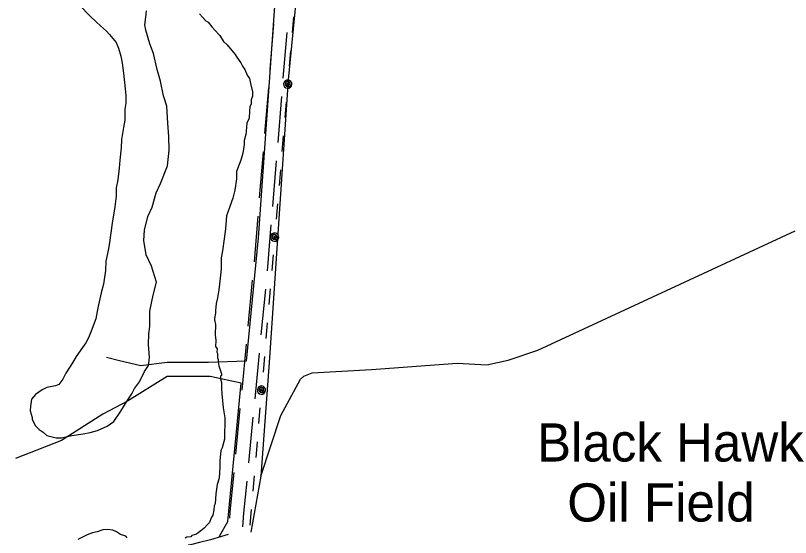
# Model space of a CAD drawing. Extents: x 3172231 to 3210228, y 940198 to 965780.
# Drawn here: x 3182155 to 3183839, y 956390 to 957526 of the extents above; entities that cross this region are included whole.
import ezdxf

# ---------------------------------------------------------------- set-up
doc = ezdxf.new("R2010")
doc.units = 0
for name, color, linetype in [('V-ROAD-CNTR', 7, 'Continuous'), ('V-SITE-VEGE', 7, 'Continuous'), ('V-TOPO-GNAM-IDEN', 7, 'Continuous'), ('V-TOPO-SHOR', 7, 'Continuous'), ('V-UTIL-LINE', 7, 'Continuous')]:
    doc.layers.add(name, color=color, linetype=linetype)

msp = doc.modelspace()

# ---------------------------------------------------------------- linework, layer by layer
at = {"layer": 'V-ROAD-CNTR'}
for p, q in [((3182708.529, 957408.331), (3182716.704, 957507.996)), ((3182737.064, 957389.243), (3182745.239, 957488.908)), ((3182697.084, 957268.799), (3182705.259, 957368.464)), ((3182725.62, 957249.712), (3182733.794, 957349.377)), ((3182685.64, 957129.268), (3182693.814, 957228.933)), ((3182714.175, 957110.18), (3182722.35, 957209.846)), ((3182674.195, 956989.736), (3182682.37, 957089.402)), ((3182660.834, 956850.376), (3182670.464, 956949.911)), ((3182689.13, 956831.31), (3182698.759, 956930.845)), ((3182647.353, 956711.027), (3182656.983, 956810.562)), ((3182675.649, 956691.961), (3182685.278, 956791.496)), ((3182633.872, 956571.677), (3182643.501, 956671.213)), ((3182662.167, 956552.611), (3182671.797, 956652.146))]:
    msp.add_line(p, q, dxfattribs=at)
for points in [[(3182702.611, 956970.659), (3182703.398, 956978.793), (3182710.905, 957070.314)], [(3182620.674, 956432.303), (3182621.717, 956446.036), (3182630.02, 956531.863)], [(3182649.31, 956413.208), (3182651.607, 956443.456), (3182658.316, 956512.797)], [(3182617.121, 956396.479), (3182602.992, 956392.242), (3182579.141, 956385.535), (3182555.135, 956379.231), (3182535.32, 956374.275), (3182535.32, 956374.569), (3182530.657, 956373.521)]]:
    msp.add_lwpolyline(points, dxfattribs=at)
at = {"layer": 'V-SITE-VEGE'}
for points in [[(3182359.713, 957032.154), (3182357.548, 957017.909), (3182351.195, 956991.473), (3182351.013, 956971.097), (3182346.671, 956941.588), (3182341.402, 956922.275), (3182333.978, 956889.737), (3182329.691, 956866.338), (3182319.254, 956838.922), (3182314.032, 956824.702), (3182307.818, 956813.551), (3182300.595, 956803.426), (3182287.175, 956784.185), (3182278.897, 956769.996), (3182264.432, 956747.71), (3182258.197, 956734.521), (3182248.928, 956723.396), (3182241.768, 956720.404), (3182223.392, 956716.492), (3182213.16, 956711.491), (3182198.801, 956701.429), (3182189.538, 956691.326), (3182187.365, 956676.058), (3182187.275, 956665.872), (3182191.222, 956651.571), (3182191.185, 956647.495), (3182198.197, 956634.185), (3182206.266, 956624.942), (3182215.39, 956619.765), (3182223.478, 956612.56), (3182243.806, 956607.283), (3182255.015, 956607.182), (3182277.475, 956612.075), (3182301.965, 956615.929), (3182317.274, 956618.85), (3182333.613, 956622.778), (3182354.083, 956632.782), (3182368.437, 956642.844), (3182382.886, 956663.093), (3182390.117, 956674.236), (3182396.331, 956685.387), (3182407.695, 956702.607), (3182413.917, 956714.778), (3182424.235, 956728.95), (3182435.644, 956751.263), (3182443.914, 956764.436), (3182446.108, 956781.739), (3182444.326, 956810.284), (3182444.535, 956833.72), (3182446.714, 956848.983), (3182447.015, 956882.605), (3182451.283, 956903.964), (3182454.457, 956917.182), (3182461.846, 956945.647), (3182450.951, 956980.387), (3182438.946, 957004.951), (3182434.135, 957036.58), (3182435.356, 957058.985), (3182442.753, 957088.468), (3182452.106, 957108.764), (3182460.542, 957140.273), (3182469.893, 957160.568), (3182485.525, 957199.148), (3182488.884, 957232.742), (3182488.131, 957262.298), (3182486.359, 957291.863), (3182483.633, 957328.57), (3182476.703, 957351.049), (3182469.852, 957382.696), (3182462.952, 957408.233), (3182455.113, 957442.946), (3182447.154, 957464.416), (3182438.249, 957494.044), (3182436.312, 957505.271), (3182438.507, 957522.573), (3182439.644, 957535.809)], [(3182294.05, 957548.326), (3182317.272, 957524.682), (3182330.408, 957512.337), (3182339.495, 957503.086), (3182352.639, 957491.758), (3182359.707, 957484.562), (3182373.815, 957467.115), (3182378.798, 957454.841), (3182383.738, 957437.474), (3182386.656, 957422.165), (3182389.521, 957400.741), (3182393.286, 957366.065), (3182395.194, 957351.782), (3182395.047, 957335.478), (3182392.89, 957322.254), (3182392.671, 957297.801), (3182389.476, 957282.545), (3182385.161, 957256.091), (3182384.997, 957237.753), (3182381.702, 957211.291), (3182380.529, 957193.979), (3182377.244, 957168.535), (3182374.03, 957151.242), (3182373.864, 957132.902), (3182372.791, 957126.799), (3182370.598, 957109.495), (3182365.185, 957073.882), (3182359.713, 957032.154)], [(3182554.729, 957529.679), (3182561.797, 957522.483), (3182568.857, 957514.268), (3182573.923, 957511.165), (3182581.982, 957500.905), (3182588.034, 957493.716), (3182599.136, 957482.407), (3182607.168, 957469.089)], [(3182607.168, 957469.089), (3182615.256, 957461.884), (3182632.394, 957441.351), (3182634.395, 957437.255), (3182641.444, 957428.025), (3182644.454, 957422.903), (3182648.464, 957415.735), (3182653.496, 957408.556), (3182658.479, 957396.285), (3182663.511, 957389.107), (3182665.448, 957377.879), (3182670.376, 957359.495), (3182670.294, 957350.326), (3182667.165, 957342.201), (3182667.091, 957334.05), (3182663.97, 957326.948), (3182663.894, 957318.797), (3182662.731, 957302.505), (3182657.537, 957291.341), (3182656.361, 957274.031), (3182655.276, 957266.909), (3182652.102, 957253.691), (3182652.03, 957245.542), (3182648.798, 957226.209), (3182644.585, 957210.963), (3182635.195, 957186.592), (3182635.05, 957170.29), (3182631.773, 957145.866), (3182627.542, 957128.583), (3182617.095, 957100.146), (3182613.945, 957089.986), (3182611.654, 957061.476), (3182608.405, 957040.105), (3182605.11, 957013.645), (3182601.915, 956998.389), (3182601.704, 956974.956), (3182600.555, 956960.702), (3182598.346, 956941.361), (3182597.215, 956929.146), (3182594.004, 956911.851), (3182590.838, 956899.653), (3182589.683, 956884.379), (3182589.627, 956878.266), (3182587.487, 956867.075), (3182587.461, 956864.02), (3182589.406, 956853.813), (3182589.205, 956831.397), (3182590.115, 956819.162), (3182589.996, 956805.916), (3182593.004, 956800.798), (3182592.941, 956793.665), (3182593.932, 956790.599), (3182593.85, 956781.428), (3182595.851, 956777.334), (3182595.804, 956772.241), (3182596.75, 956764.079), (3182602.708, 956746.704), (3182602.671, 956742.629), (3182600.625, 956741.629), (3182600.57, 956735.516), (3182602.534, 956727.347), (3182602.415, 956714.102), (3182603.333, 956702.885), (3182605.233, 956687.585), (3182606.114, 956672.292), (3182609.997, 956650.86), (3182609.577, 956603.991), (3182604.316, 956585.699), (3182601.205, 956579.612), (3182598.966, 956557.217), (3182598.845, 956543.971), (3182597.608, 956519.528), (3182593.404, 956505.3), (3182590.164, 956484.951), (3182590.072, 956474.763), (3182588.954, 956463.564), (3182586.879, 956459.507), (3182585.777, 956450.346), (3182583.639, 956439.158), (3182580.526, 956433.071), (3182576.36, 956422.92), (3182572.248, 956418.883), (3182565.039, 956410.795), (3182557.853, 956404.746), (3182551.707, 956400.725), (3182548.622, 956397.696), (3182538.405, 956394.733), (3182536.34, 956391.694), (3182527.161, 956390.758), (3182524.087, 956388.747)], [(3182394.719, 956392.968), (3182383.549, 956397.143), (3182374.426, 956402.321), (3182366.311, 956406.47), (3182354.093, 956407.598), (3182344.916, 956406.663), (3182332.652, 956402.696), (3182322.445, 956400.75), (3182311.191, 956395.757), (3182290.724, 956385.752)], [(3182397.746, 956389.883), (3182394.719, 956392.968)]]:
    msp.add_lwpolyline(points, dxfattribs=at)
at = {"layer": 'V-TOPO-SHOR'}
for points in [[(3182822.586, 958734.934), (3182778.258, 958176.724), (3182737.969, 957804.61), (3182723.193, 957618.54), (3182682.4, 957042.425), (3182656.684, 956774.066), (3182574.359, 956770.69), (3182484.885, 956770.911), (3182427.604, 956763.895), (3182381.104, 956774.747), (3182352.49, 956781.976)], [(3182854.814, 958742.013), (3182813.915, 958122.951), (3182777.055, 957689.986), (3182747.671, 957385.846), (3182706.807, 956781.1), (3182688.275, 956523.459), (3182666.5, 956401.828)], [(3182688.275, 956523.459), (3182731.55, 956655.774), (3182774.692, 956734.405), (3182781.868, 956741.545), (3182799.78, 956748.659), (3182928.64, 956755.498), (3183114.781, 956769.354), (3183179.193, 956765.616), (3183225.746, 956776.238), (3183290.221, 956797.552), (3183849.183, 957057.435)], [(3182598.478, 956393.049), (3182616.452, 956425.215), (3182645.827, 956725.776), (3182577.863, 956740.26), (3182502.705, 956740.446), (3182484.81, 956740.49), (3182398.782, 956687.018), (3182345.027, 956658.52), (3182255.412, 956601.478), (3182201.674, 956580.137), (3182155.104, 956562.357)]]:
    msp.add_lwpolyline(points, dxfattribs=at)
at = {"layer": 'V-UTIL-LINE'}
for points in [[(3182759.205, 957522.986), (3182756.311, 957489.109)], [(3182752.907, 957449.254), (3182750.013, 957415.377)], [(3182746.695, 957376.534), (3182749.192, 957377.964), (3182747.086, 957378.955), (3182744.739, 957377.53), (3182744.814, 957374.603), (3182748.182, 957374.154), (3182751.84, 957377.086), (3182750.398, 957381.103), (3182745.837, 957382.791), (3182742.193, 957380.019), (3182740.855, 957375.753), (3182743.6, 957371.786), (3182749.048, 957370.997), (3182755.662, 957375.768), (3182755.273, 957379.258), (3182753.578, 957382.333), (3182750.834, 957384.526), (3182747.461, 957385.502), (3182743.971, 957385.112), (3182740.896, 957383.417), (3182738.703, 957380.673), (3182737.728, 957377.3), (3182738.117, 957373.81), (3182739.812, 957370.735), (3182742.556, 957368.542), (3182745.929, 957367.567), (3182749.419, 957367.956), (3182752.494, 957369.652), (3182754.687, 957372.395), (3182755.662, 957375.768)], [(3182743.374, 957337.66), (3182743.329, 957337.128), (3182740.471, 957303.784)], [(3182737.055, 957263.93), (3182734.151, 957230.054)], [(3182730.735, 957190.201), (3182727.831, 957156.325)], [(3182724.415, 957116.471), (3182721.511, 957082.595)], [(3182718.182, 957043.754), (3182720.679, 957045.183), (3182718.574, 957046.175), (3182716.226, 957044.751), (3182716.3, 957041.824), (3182719.668, 957041.374), (3182723.327, 957044.305), (3182721.886, 957048.322), (3182717.326, 957050.011), (3182713.681, 957047.241), (3182712.342, 957042.975), (3182715.085, 957039.008), (3182720.533, 957038.216), (3182727.149, 957042.986), (3182726.76, 957046.476), (3182725.066, 957049.552), (3182722.323, 957051.745), (3182718.95, 957052.722), (3182715.46, 957052.333), (3182712.384, 957050.639), (3182710.191, 957047.896), (3182709.215, 957044.523), (3182709.603, 957041.033), (3182711.297, 957037.957), (3182714.04, 957035.764), (3182717.413, 957034.787), (3182720.903, 957035.176), (3182723.979, 957036.87), (3182726.172, 957039.613), (3182727.149, 957042.986)], [(3182714.849, 957004.88), (3182711.945, 956971.004)], [(3182708.529, 956931.15), (3182705.625, 956897.274)], [(3182702.209, 956857.421), (3182699.305, 956823.545)], [(3182695.889, 956783.691), (3182692.985, 956749.815)], [(3182689.657, 956710.976), (3182692.154, 956712.405), (3182690.049, 956713.396), (3182687.701, 956711.972), (3182687.775, 956709.045), (3182691.143, 956708.595), (3182694.802, 956711.526), (3182693.361, 956715.543), (3182688.801, 956717.233), (3182685.156, 956714.462), (3182683.817, 956710.197), (3182686.56, 956706.229), (3182692.008, 956705.438), (3182698.624, 956710.207), (3182698.235, 956713.697), (3182696.541, 956716.773), (3182693.798, 956718.966), (3182690.425, 956719.943), (3182686.935, 956719.555), (3182683.859, 956717.86), (3182681.666, 956715.117), (3182680.69, 956711.744), (3182681.078, 956708.255), (3182682.772, 956705.179), (3182685.515, 956702.985), (3182688.888, 956702.009), (3182692.378, 956702.397), (3182695.454, 956704.092), (3182697.647, 956706.834), (3182698.624, 956710.207)], [(3182686.323, 956672.1), (3182683.419, 956638.224)], [(3182680.003, 956598.37), (3182677.099, 956564.494)], [(3182673.683, 956524.641), (3182670.779, 956490.765)], [(3182667.363, 956450.911), (3182664.459, 956417.035)]]:
    msp.add_lwpolyline(points, dxfattribs=at)

# ---------------------------------------------------------------- texts
at = {"layer": 'V-TOPO-GNAM-IDEN'}
for s, p in [('Black Hawk', (3183288.317, 956555.58)), ('Oil Field', (3183354.166, 956425.064))]:
    msp.add_text(s, height=82.9998, dxfattribs=at).set_placement(p)

doc.saveas('drawing.dxf')
